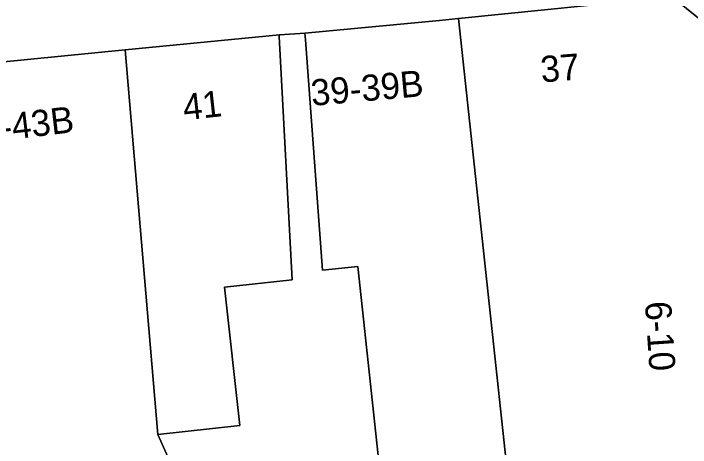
# Model space of a CAD drawing. Extents: x 159960 to 160866, y 382700 to 383354.
# Drawn here: x 160036.23 to 160062.11, y 383263.3 to 383279.88 of the extents above; entities that cross this region are included whole.
import ezdxf

# ---------------------------------------------------------------- set-up
doc = ezdxf.new("R2010")
doc.units = 0
for name, color, linetype in [('IMGEO_Erf', 7, 'Continuous'), ('IMGEO_Pand', 7, 'Continuous'), ('IMGEO_Pand_nummerreeks', 7, 'Continuous'), ('IMGEO_Voetpad_open', 7, 'Continuous')]:
    doc.layers.add(name, color=color, linetype=linetype)

msp = doc.modelspace()

# ---------------------------------------------------------------- linework, layer by layer
at = {"layer": 'IMGEO_Erf'}
msp.add_lwpolyline([(160051.209, 383253.408), (160049.395, 383270.222), (160048.043, 383270.074), (160047.391, 383278.876), (160047.368, 383279.124), (160046.395, 383279.069), (160046.392, 383278.999), (160046.889, 383269.71), (160044.3, 383269.424), (160044.883, 383264.141), (160041.745, 383263.795), (160042.73, 383261.604)], dxfattribs=at)
at = {"layer": 'IMGEO_Pand'}
for points in [[(160063.376, 383271.746), (160062.564, 383279.089), (160062.511, 383279.566), (160062.543, 383279.597), (160061.373, 383280.559), (160061.342, 383280.521), (160053.242, 383279.684), (160056.017, 383253.898), (160065.133, 383254.986), (160064.297, 383262.679)], [(160053.242, 383279.684), (160052.517, 383279.609), (160047.368, 383279.124), (160047.391, 383278.876), (160048.043, 383270.074), (160049.395, 383270.222), (160051.209, 383253.408), (160056.017, 383253.898)], [(160046.392, 383278.999), (160046.395, 383279.069), (160040.495, 383278.49), (160041.745, 383263.795), (160044.883, 383264.141), (160044.3, 383269.424), (160046.889, 383269.71)], [(160040.495, 383278.49), (160034.427, 383277.894), (160034.451, 383277.646), (160035.818, 383262.243), (160038.03, 383254.521), (160038.602, 383251.781), (160043.484, 383252.16), (160042.76, 383261.226), (160042.73, 383261.604), (160041.745, 383263.795)]]:
    msp.add_lwpolyline(points, close=True, dxfattribs=at)
at = {"layer": 'IMGEO_Voetpad_open'}
msp.add_lwpolyline([(159996.758, 383283.546), (160000, 383283.499), (160019.606, 383283.216), (160020.642, 383277.254), (160021.414, 383277.287), (160027.145, 383277.532), (160033.368, 383277.799), (160034.427, 383277.894), (160040.495, 383278.49), (160046.395, 383279.069), (160047.368, 383279.124), (160052.517, 383279.609), (160053.242, 383279.684), (160061.342, 383280.521), (160061.373, 383280.559), (160062.543, 383279.597), (160066.298, 383280.383), (160065.906, 383283.389)], dxfattribs=at)

# ---------------------------------------------------------------- texts
at = {"layer": 'IMGEO_Pand_nummerreeks'}
for s, rotation, p in [('37', 4.5837, (160056.418, 383277.244)), ('39-39B', 5.0535, (160047.642, 383276.348)), ('41', 6.2911, (160042.758, 383275.797)), ('43-43B', 6.7666, (160034.302, 383274.846)), ('6-10', 273.8844, (160060.369, 383268.86))]:
    msp.add_text(s, height=1, rotation=rotation, dxfattribs=at).set_placement(p)

doc.saveas('drawing.dxf')
